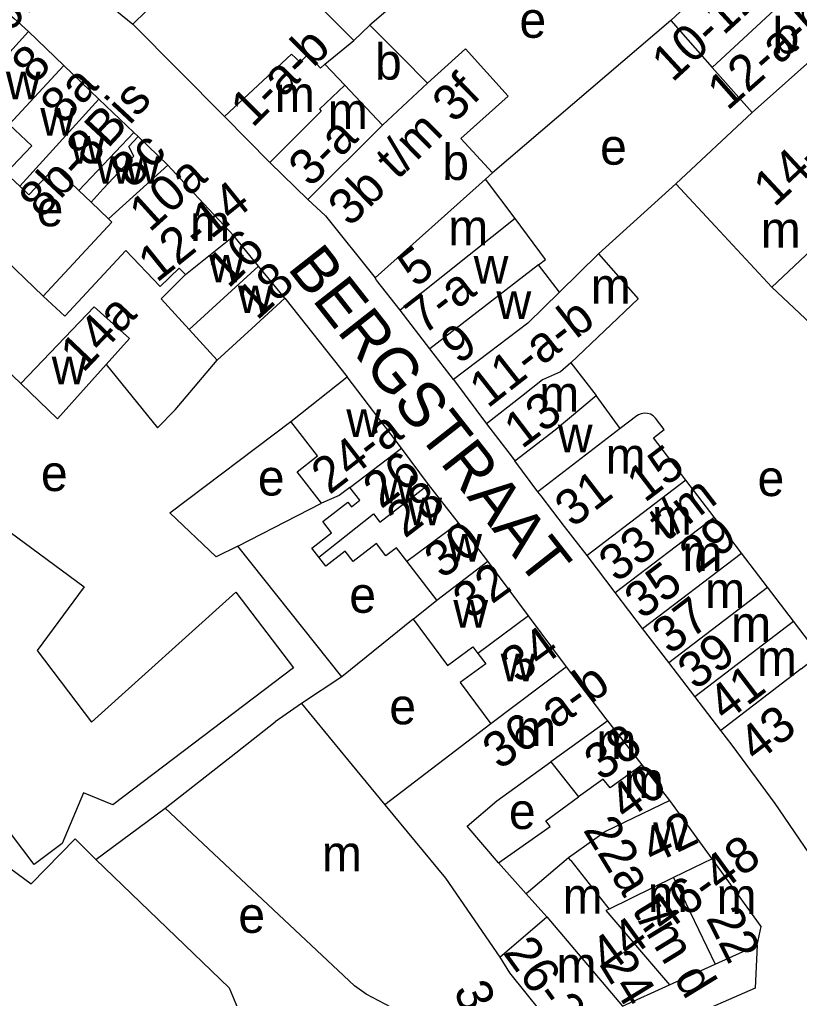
# Model space of a CAD drawing. Extents: x 160673 to 161924, y 382258 to 384145.
# Drawn here: x 161158.4 to 161245.1, y 383003.9 to 383112.8 of the extents above; entities that cross this region are included whole.
import ezdxf

# ---------------------------------------------------------------- set-up
doc = ezdxf.new("R2010")
doc.units = 0
for name, color, linetype in [('BLT_Basislijn', 7, 'Continuous'), ('BLT_Bebouwing', 7, 'Continuous'), ('BLT_Centroide', 7, 'Continuous'), ('BLT_Huisnummer', 7, 'Continuous'), ('BLT_Huisnummer_ tussenligend', 7, 'Continuous'), ('BLT_Huisnummer_reeks', 7, 'Continuous'), ('BLT_Onderdoorgang_en_onderverdeling', 7, 'Continuous'), ('BLT_Onderverdeling_panden', 7, 'Continuous'), ('BLT_Straatnaam', 7, 'Continuous'), ('BLT_Straatnaam_hoofdweg', 7, 'Continuous')]:
    doc.layers.add(name, color=color, linetype=linetype)

msp = doc.modelspace()

# ---------------------------------------------------------------- linework, layer by layer
at = {"layer": 'BLT_Basislijn'}
for p, q in [((161204.09, 383117.92), (161197.35, 383112.16)), ((161230.82, 383112.67), (161211.01, 383095.71)), ((161222.81, 383086.73), (161231.38, 383094.5)), ((161161.04, 383082.01), (161152.88, 383089.86)), ((161242.08, 383083.02), (161250.6, 383074.96)), ((161187.93, 383081.8), (161194.84, 383073.04)), ((161182.68, 383054.22), (161191.99, 383058.99)), ((161202.2, 383046.09), (161194.24, 383039.68)), ((161194.24, 383039.68), (161189.75, 383036.71))]:
    msp.add_line(p, q, dxfattribs=at)
for points in [[(161166.06, 383116.33), (161171.02, 383112.24)], [(161150.23, 383070.53), (161154.97, 383075.72), (161158.54, 383072.29)], [(161168.05, 383074.42), (161173.75, 383067.37), (161175.72, 383069.38), (161180.39, 383074.91)], [(161182.68, 383054.22), (161180.27, 383053.03), (161175.13, 383057.9), (161188.59, 383068.09)], [(161194.24, 383039.68), (161182.68, 383054.22)], [(161147.07, 383025.97), (161159.71, 383016.67), (161164.6, 383021.65), (161166.91, 383019.35)], [(161166.91, 383019.35), (161174.59, 383025.07)], [(161166.91, 383019.35), (161181.74, 383005.1), (161182.84, 383002.43)], [(161240.43, 383009.86), (161240.2, 383005.06), (161224.27, 382998.11), (161174.47, 382977.28), (161137.52, 382962.54)]]:
    msp.add_lwpolyline(points, dxfattribs=at)
at = {"layer": 'BLT_Bebouwing'}
for p, q in [((161171.02, 383112.24), (161182.46, 383123.62)), ((161182.46, 383123.62), (161195.6, 383110.42)), ((161181.21, 383102), (161171.02, 383112.24)), ((161230.82, 383112.67), (161235.45, 383107.44)), ((161159.39, 383111.43), (161163.35, 383107.64)), ((161195.6, 383110.42), (161197.35, 383112.16)), ((161163.35, 383107.64), (161167.23, 383103.93)), ((161235.45, 383107.44), (161239.88, 383102.45)), ((161167.23, 383103.93), (161171.12, 383100.21)), ((161239.88, 383102.45), (161231.38, 383094.5)), ((161186.23, 383096.86), (161181.21, 383102)), ((161171.12, 383100.21), (161171.6, 383099.75)), ((161174.91, 383096.57), (161171.6, 383099.75)), ((161177.25, 383094.07), (161174.91, 383096.57)), ((161190.48, 383092.76), (161186.23, 383096.86)), ((161211.01, 383095.71), (161210.24, 383095.03)), ((161213.53, 383090.66), (161210.24, 383095.03)), ((161165.02, 383093.75), (161166.36, 383092.47)), ((161182.23, 383088.73), (161177.25, 383094.07)), ((161231.38, 383094.5), (161235.8, 383089.76)), ((161168.32, 383090.6), (161166.36, 383092.47)), ((161235.8, 383089.76), (161242.08, 383083.02)), ((161222.81, 383086.73), (161218.46, 383082.47)), ((161242.08, 383083.02), (161246.45, 383087.11)), ((161187.93, 383081.8), (161184.99, 383085.36)), ((161204.03, 383076.15), (161200.72, 383080.44)), ((161177.28, 383078.32), (161180.39, 383074.91)), ((161206.68, 383072.73), (161204.03, 383076.15)), ((161200.87, 383065.12), (161194.84, 383073.04)), ((161206.68, 383072.73), (161210.34, 383067.8)), ((161225.22, 383067.28), (161222.54, 383070.95)), ((161227.07, 383068.7), (161225.22, 383067.28)), ((161227.23, 383068.8), (161227.07, 383068.7)), ((161227.23, 383068.8), (161227.23, 383068.8)), ((161203.89, 383061.08), (161200.87, 383065.12)), ((161216.06, 383060.25), (161213.48, 383063.68)), ((161207.21, 383056.8), (161203.89, 383061.08)), ((161235.64, 383057.43), (161232.5, 383061.54)), ((161238.69, 383053.43), (161235.64, 383057.43)), ((161221.52, 383053.16), (161219.01, 383056.39)), ((161200.33, 383054.04), (161199.16, 383053.13)), ((161201.49, 383052.53), (161200.33, 383054.04)), ((161204.83, 383048.2), (161201.49, 383052.53)), ((161215.01, 383046.45), (161210.48, 383052.55)), ((161224.66, 383049.05), (161221.52, 383053.16)), ((161227.7, 383045.06), (161224.66, 383049.05)), ((161219.23, 383040.78), (161215.01, 383046.45)), ((161230.6, 383041.28), (161227.7, 383045.06)), ((161233.49, 383037.5), (161230.6, 383041.28)), ((161236.39, 383033.73), (161233.49, 383037.5)), ((161189.75, 383036.71), (161186.84, 383034.66)), ((161189.75, 383036.71), (161194.88, 383030.5)), ((161182.48, 383031.21), (161186.84, 383034.66)), ((161210.82, 383034.46), (161199.04, 383025.46)), ((161227.66, 383029.89), (161223.82, 383034.8)), ((161174.59, 383025.07), (161182.48, 383031.21)), ((161194.88, 383030.5), (161199.04, 383025.46)), ((161217.51, 383030.21), (161220.57, 383026.32)), ((161230.73, 383025.92), (161227.66, 383029.89)), ((161211.66, 383019.01), (161208.19, 383023.09)), ((161211.66, 383019.01), (161217.43, 383023.04)), ((161235.76, 383007.73), (161240.43, 383009.86)), ((161230.68, 383005.42), (161235.76, 383007.73)), ((161225.45, 383003.05), (161230.68, 383005.42))]:
    msp.add_line(p, q, dxfattribs=at)
for points in [[(161241.87, 383122.97), (161238.21, 383119.57), (161230.82, 383112.67)], [(161135.95, 383110.3), (161145.53, 383120.49), (161147.95, 383120.82), (161150.4, 383118.88), (161157.82, 383112.89), (161159.39, 383111.43)], [(161203.77, 383105.7), (161200.87, 383108.61), (161197.35, 383112.16)], [(161203.77, 383105.7), (161208.02, 383109.53), (161212.75, 383104.26), (161207.5, 383099.54), (161211.01, 383095.71)], [(161157.26, 383101.11), (161159.79, 383098.71), (161156.9, 383095.68), (161158.44, 383094.23)], [(161158.44, 383094.23), (161159.46, 383093.27), (161162.34, 383096.31), (161165.02, 383093.75)], [(161190.48, 383092.76), (161192.42, 383090.96), (161197.97, 383084.05)], [(161168.32, 383090.6), (161168.67, 383090.23), (161161.04, 383082.01)], [(161216.12, 383085.49), (161216.91, 383086.1), (161213.53, 383090.66)], [(161184.99, 383085.36), (161182.23, 383088.73)], [(161161.04, 383082.01), (161163.45, 383079.77), (161170.22, 383087.07)], [(161170.22, 383087.07), (161174.05, 383083.1), (161176.15, 383085.12), (161176.85, 383084.4)], [(161222.81, 383086.73), (161227.22, 383081.71), (161219.71, 383074.6)], [(161218.46, 383082.47), (161216.12, 383085.49)], [(161176.85, 383084.4), (161174.17, 383081.73), (161177.28, 383078.32)], [(161200.72, 383080.44), (161198.12, 383083.8), (161197.97, 383084.05)], [(161180.39, 383074.91), (161184.23, 383078.42), (161187.93, 383081.8)], [(161168.05, 383074.42), (161170.63, 383077.31), (161166.71, 383080.82), (161158.54, 383072.29)], [(161158.54, 383072.29), (161162.63, 383068.38), (161168.05, 383074.42)], [(161219.71, 383074.6), (161222.54, 383070.95)], [(161188.59, 383068.09), (161194.84, 383073.04)], [(161229.12, 383068.46), (161228.87, 383068.69), (161228.57, 383068.87), (161228.24, 383068.97), (161227.9, 383068.99), (161227.55, 383068.94), (161227.23, 383068.8)], [(161191.99, 383058.99), (161189.28, 383062.49), (161191.56, 383064.25), (161188.59, 383068.09)], [(161210.34, 383067.8), (161213.07, 383064.24), (161213.48, 383063.68)], [(161232.5, 383061.54), (161228.9, 383066.26), (161230.1, 383067.17), (161229.12, 383068.46)], [(161142.9, 383063.27), (161145.9, 383061.07), (161147.38, 383063.09), (161165.58, 383049.68), (161160.36, 383042.62), (161166.42, 383034.63), (161182.45, 383049.09), (161188.86, 383040.67), (161168.78, 383025.44), (161165.52, 383026.79), (161163.14, 383021.14), (161160.04, 383018.81), (161151.05, 383030.64)], [(161191.7, 383052.99), (161190.93, 383053.99), (161193.1, 383055.68), (161192.12, 383056.94), (161194.91, 383059.1), (161195.31, 383058.58), (161196.26, 383059.32), (161195.15, 383060.75)], [(161195.15, 383060.75), (161193.96, 383059.84), (161191.99, 383058.99)], [(161219.01, 383056.39), (161216.4, 383059.79), (161216.06, 383060.25)], [(161210.48, 383052.55), (161207.21, 383056.8)], [(161199.16, 383053.13), (161198.1, 383054.51), (161195.52, 383052.51), (161194.63, 383053.67), (161192.47, 383052), (161191.7, 383052.99)], [(161241.58, 383049.65), (161238.69, 383053.43)], [(161244.47, 383045.86), (161241.58, 383049.65)], [(161202.2, 383046.09), (161204.83, 383048.2)], [(161202.2, 383046.09), (161206, 383040.94), (161208.81, 383043.02), (161209.38, 383042.28)], [(161245.34, 383040.57), (161247.33, 383042.11), (161244.47, 383045.86)], [(161209.38, 383042.28), (161210.25, 383041.14), (161207.42, 383039.05), (161210.82, 383034.46)], [(161223.82, 383034.8), (161223.64, 383035.02), (161219.23, 383040.78)], [(161248.41, 383016.84), (161242.43, 383025.6), (161237.65, 383032.08), (161236.39, 383033.73)], [(161208.19, 383023.09), (161211.48, 383025.9), (161217.51, 383030.21)], [(161217.43, 383023.04), (161216.95, 383023.68), (161220.57, 383026.32)], [(161235.44, 383019.43), (161230.73, 383025.92)], [(161200.46, 383002.55), (161196.97, 383004.38), (161195.65, 383005.33), (161174.59, 383025.07)], [(161240.43, 383009.86), (161240.89, 383011.93), (161235.44, 383019.43)]]:
    msp.add_lwpolyline(points, dxfattribs=at)
at = {"layer": 'BLT_Onderdoorgang_en_onderverdeling'}
for p, q in [((161174.91, 383096.57), (161168.32, 383090.6)), ((161225.22, 383067.28), (161216.06, 383060.25))]:
    msp.add_line(p, q, dxfattribs=at)
for points in [[(161166.36, 383092.47), (161167.72, 383093.93), (161171.13, 383097.58), (161170.57, 383098.66), (161171.6, 383099.75)], [(161213.48, 383063.68), (161217.98, 383067.16), (161222.54, 383070.95)]]:
    msp.add_lwpolyline(points, dxfattribs=at)
at = {"layer": 'BLT_Onderverdeling_panden'}
for p, q in [((161246.62, 383117.82), (161235.45, 383107.44)), ((161239.88, 383102.45), (161251.04, 383112.37)), ((161159.39, 383111.43), (161150.57, 383101.73)), ((161192.36, 383107.82), (161195.6, 383110.42)), ((161194.58, 383105.47), (161192.36, 383107.82)), ((161157.26, 383101.11), (161163.35, 383107.64)), ((161203.77, 383105.7), (161198.79, 383101.03)), ((161194.58, 383105.47), (161198.79, 383101.03)), ((161158.44, 383094.23), (161167.23, 383103.93)), ((161171.12, 383100.21), (161165.02, 383093.75)), ((161198.79, 383101.03), (161190.48, 383092.76)), ((161213.53, 383090.66), (161200.72, 383080.44)), ((161176.85, 383084.4), (161182.23, 383088.73)), ((161177.28, 383078.32), (161184.99, 383085.36)), ((161216.12, 383085.49), (161204.03, 383076.15)), ((161195.15, 383060.75), (161200.87, 383065.12)), ((161232.5, 383061.54), (161221.52, 383053.16)), ((161224.66, 383049.05), (161235.64, 383057.43)), ((161227.7, 383045.06), (161238.69, 383053.43)), ((161204.83, 383048.2), (161210.48, 383052.55)), ((161230.6, 383041.28), (161241.58, 383049.65)), ((161215.01, 383046.45), (161209.38, 383042.28)), ((161233.49, 383037.5), (161244.47, 383045.86)), ((161219.23, 383040.78), (161210.82, 383034.46)), ((161245.34, 383040.57), (161236.39, 383033.73)), ((161223.82, 383034.8), (161217.51, 383030.21)), ((161230.73, 383025.92), (161223.57, 383022.48)), ((161211.66, 383019.01), (161214.76, 383015.55)), ((161219.46, 383019.55), (161214.76, 383015.55)), ((161219.7, 383019.25), (161222.97, 383015.1)), ((161235.44, 383019.43), (161231.14, 383017.35)), ((161231.14, 383017.35), (161223.97, 383013.83)), ((161231.14, 383017.35), (161235.76, 383007.73)), ((161214.76, 383015.55), (161217.04, 383012.99)), ((161222.97, 383015.1), (161223.97, 383013.83)), ((161223.61, 383013.68), (161230.68, 383005.42)), ((161211.82, 383008.5), (161217.04, 383012.99)), ((161217.04, 383012.99), (161225.45, 383003.05))]:
    msp.add_line(p, q, dxfattribs=at)
for points in [[(161192.36, 383107.82), (161191.87, 383107.35), (161190.47, 383108.87), (161189.61, 383108.03), (161188.67, 383108.92), (161181.21, 383102)], [(161194.58, 383105.47), (161191.76, 383102.81), (161191.96, 383102.57), (161186.23, 383096.86)], [(161197.97, 383084.05), (161210.24, 383095.03)], [(161218.46, 383082.47), (161214.94, 383079.02), (161210.65, 383075.76), (161206.68, 383072.73)], [(161219.71, 383074.6), (161218.57, 383073.58), (161216.57, 383072.69), (161214.23, 383070.86), (161210.34, 383067.8)], [(161191.7, 383052.99), (161197.76, 383057.8), (161198.48, 383056.86), (161203.89, 383061.08)], [(161201.49, 383052.53), (161207.21, 383056.8)], [(161227.66, 383029.89), (161224.1, 383027.34), (161223.31, 383028.31), (161220.57, 383026.32)], [(161199.04, 383025.46), (161205.77, 383017.31), (161211.82, 383008.5)], [(161223.57, 383022.48), (161222.38, 383021.63)], [(161222.38, 383021.63), (161219.46, 383019.55)], [(161219.7, 383019.25), (161219.46, 383019.55)], [(161223.97, 383013.83), (161223.61, 383013.68)], [(161211.82, 383008.5), (161212.9, 383006.76), (161218.03, 383000.37), (161218.39, 382999.84)]]:
    msp.add_lwpolyline(points, dxfattribs=at)

# ---------------------------------------------------------------- texts
at = {"layer": 'BLT_Centroide'}
for s, p in [('e', (161214, 383110.74)), ('b', (161242.15, 383109)), ('b', (161197.94, 383106.09)), ('w', (161156.89, 383103.9)), ('m', (161186.8, 383102.47)), ('m', (161192.69, 383100.61)), ('w', (161160.72, 383099.86)), ('w', (161164.03, 383096.75)), ('b', (161205.42, 383094.93)), ('e', (161222.97, 383096.63)), ('w', (161166.91, 383094.5)), ('w', (161170.18, 383094.5)), ('e', (161160.31, 383089.78)), ('m', (161177.38, 383088.16)), ('m', (161206.08, 383087.66)), ('m', (161240.83, 383087.42)), ('w', (161179.48, 383083.53)), ('w', (161208.91, 383083.41)), ('m', (161221.93, 383081.16)), ('w', (161182.69, 383080.12)), ('w', (161211.45, 383079.47)), ('w', (161161.99, 383072.22)), ('m', (161216.2, 383069.16)), ('w', (161194.75, 383066.36)), ('w', (161218.27, 383064.66)), ('m', (161223.58, 383062.28)), ('e', (161160.79, 383060.34)), ('e', (161184.91, 383059.84)), ('e', (161240.48, 383059.78)), ('w', (161198.5, 383058.97)), ('w', (161201.52, 383056.53)), ('m', (161228.73, 383055.49)), ('w', (161205.97, 383052.5)), ('m', (161232.12, 383051.43)), ('m', (161234.65, 383047.34)), ('e', (161195.08, 383046.8)), ('w', (161206.65, 383045.16)), ('m', (161237.54, 383043.56)), ('m', (161240.41, 383039.78)), ('w', (161211.92, 383039.18)), ('e', (161199.53, 383034.4)), ('m', (161213.62, 383031.97)), ('m', (161222.56, 383030.56)), ('m', (161225.6, 383026.19)), ('e', (161212.83, 383022.76)), ('w', (161228.88, 383020.44)), ('m', (161192.03, 383018.05)), ('m', (161218.8, 383013.34)), ('m', (161228.28, 383013.53)), ('m', (161235.92, 383013.31)), ('e', (161182.74, 383011.21)), ('m', (161218.12, 383005.67))]:
    msp.add_text(s, height=4, dxfattribs=at).set_placement(p)
at = {"layer": 'BLT_Huisnummer'}
for s, rotation, p in [('8', 47.025, (161160.1, 383105.45)), ('8a', 47.025, (161163.3, 383100.95)), ('8c', 47.025, (161171.07, 383093.81)), ('5', 37.2701, (161202.45, 383082.88)), ('18', 42.414, (161184.82, 383079.22)), ('14a', 46.414, (161165.47, 383073.39)), ('9', 37.2701, (161207.23, 383074.32)), ('31', 37.4437, (161219.93, 383056.18)), ('30', 37.5524, (161205.43, 383050.47)), ('35', 37.3053, (161227.66, 383045.97)), ('34', 35.9809, (161213.87, 383038.83)), ('39', 37.2701, (161233.58, 383038.11)), ('38', 35.9809, (161223.11, 383027.99)), ('42', 25.7565, (161228.82, 383018.77)), ('24', 301.4291, (161222.8, 383007.76))]:
    msp.add_text(s, height=4, rotation=rotation, dxfattribs=at).set_placement(p)
at = {"layer": 'BLT_Huisnummer_ tussenligend'}
for s, rotation, p in [('16', 43.8648, (161181.63, 383082.78)), ('13', 37.2701, (161214.27, 383064.94)), ('26', 37.7479, (161198.62, 383058.27)), ('28', 37.5583, (161201.25, 383055)), ('33', 37.3043, (161224.81, 383050.07)), ('32', 35.9851, (161208.52, 383045.95)), ('37', 37.2701, (161230.73, 383042.05)), ('41', 37.2701, (161236.92, 383034.56)), ('40', 35.9809, (161225.87, 383023.56))]:
    msp.add_text(s, height=4, rotation=rotation, dxfattribs=at).set_placement(p)
at = {"layer": 'BLT_Huisnummer_reeks'}
for s, rotation, p in [('10-12c-12e', 42.6727, (161231.01, 383105.69)), ('12-a-b-d', 41.3852, (161237.13, 383102.55)), ('2t/m6b', 46.7678, (161150.09, 383103.54)), ('1-a-b', 44.8502, (161184.32, 383100.64)), ('14-a t/m r', 42.9818, (161242.34, 383091.8)), ('3b t/m 3f', 44.8542, (161195.16, 383089.61)), ('8b-8Bis', 47.025, (161160.91, 383090.5)), ('3-a', 44.8542, (161190.76, 383094)), ('10a', 42.1849, (161172.89, 383089.02)), ('12-14', 38.7972, (161173.67, 383083.43)), ('7-a', 37.6812, (161203.31, 383077.59)), ('11-a-b', 38.1453, (161210.47, 383069.46)), ('24-a', 37.7768, (161192.87, 383059.86)), ('15', 37.3043, (161227.92, 383058.97)), ('t/m', 37.3045, (161230.32, 383054.63)), ('29', 37.407, (161233.77, 383051.05)), ('36-a-b', 35.9793, (161211.8, 383029.25)), ('43', 37.408, (161240.34, 383030.04)), ('22a t/m d', 301.4291, (161221.02, 383022.66)), ('44-46-48', 35.981, (161223.78, 383006.54)), ('22', 296.7119, (161234.7, 383012.86)), ('26-28', 305.9846, (161212.1, 383008.99)), ('30-a', 292.3109, (161206.64, 383004.89))]:
    msp.add_text(s, height=4, rotation=rotation, dxfattribs=at).set_placement(p)
at = {"layer": 'BLT_Straatnaam'}
msp.add_text('BERGSTRAAT', height=5, rotation=308.1491, dxfattribs=at).set_placement((161188.11, 383085.11))
at = {"layer": 'BLT_Straatnaam_hoofdweg'}
msp.add_text('KEIZERSGRACHT', height=8, rotation=314.6195, dxfattribs=at).set_placement((161204.86, 383174.43))

doc.saveas('drawing.dxf')
